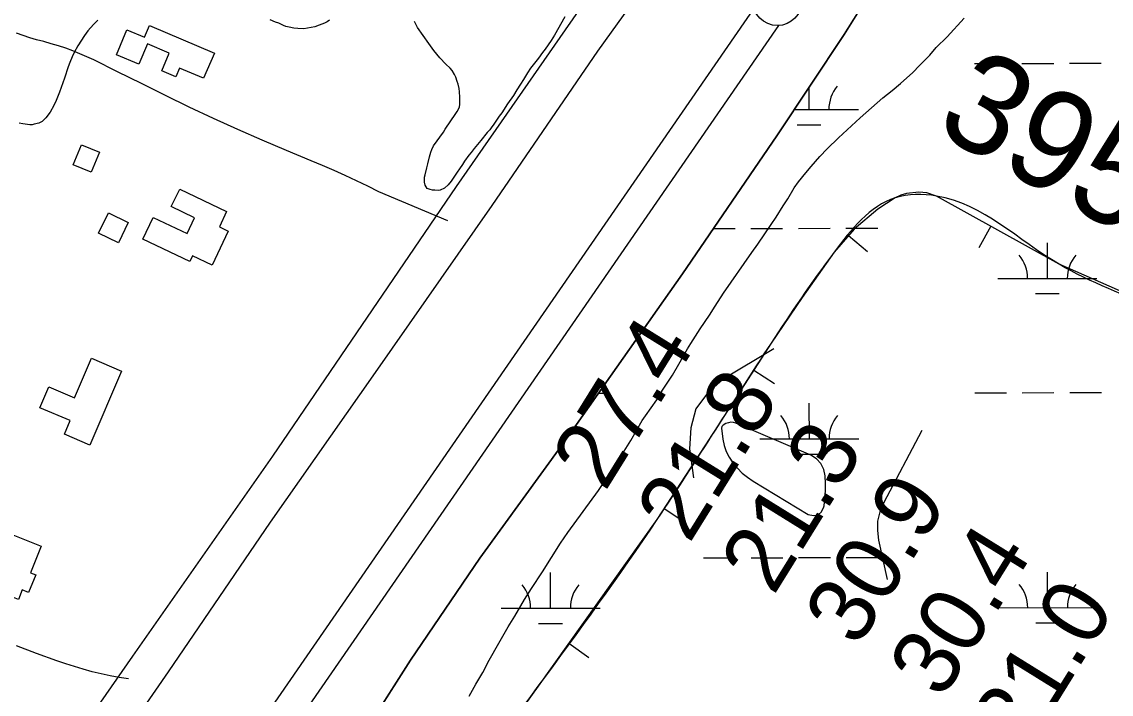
# Model space of a CAD drawing. Extents: x 3297716 to 3335574, y 688621 to 713991.
# Drawn here: x 3317812 to 3318912, y 694446 to 695125 of the extents above; entities that cross this region are included whole.
import ezdxf

# ---------------------------------------------------------------- set-up
doc = ezdxf.new("R2010")
doc.units = 0
for name, color, linetype in [('V-BLDG-OTLN', 7, 'Continuous'), ('V-BORW-LINE', 7, 'Continuous'), ('V-LEVE-TOET', 7, 'Continuous'), ('V-RIVR-RANG', 7, 'Continuous'), ('V-ROAD-CNTR', 7, 'Continuous'), ('V-SITE-VEGE', 7, 'Continuous'), ('V-SURV-IDEN', 7, 'Continuous'), ('V-SURV-LINE', 7, 'Continuous'), ('V-TOPO-MAJR', 7, 'Continuous'), ('V-TOPO-MINR', 7, 'Continuous'), ('V-WETL-SWMP', 7, 'Continuous')]:
    doc.layers.add(name, color=color, linetype=linetype)

msp = doc.modelspace()

# ---------------------------------------------------------------- linework, layer by layer
at = {"layer": 'V-BLDG-OTLN'}
for points in [[(3317941.1, 695121.1), (3318006.6, 695093.3), (3317995.8, 695067.8), (3317971.5, 695078.1), (3317967.8, 695069.4), (3317953.6, 695075.4), (3317961.1, 695093.2), (3317939.1, 695102.5), (3317930.4, 695081.9), (3317907.7, 695091.5), (3317918.4, 695116.8), (3317936.1, 695109.3)], [(3317872.3, 695000.6), (3317890.5, 694993.2), (3317882.2, 694972.8), (3317864, 694980.2)], [(3317981.9, 694882.7), (3317934.4, 694905.4), (3317944.8, 694927.2), (3317979, 694910.9), (3317986.7, 694926.8), (3317963.1, 694938.1), (3317971.6, 694955.8), (3318019, 694933.1), (3318011.7, 694917.8), (3318020.7, 694913.5), (3318004.3, 694879.1), (3317984.6, 694888.5)], [(3317889.7, 694911.4), (3317899.7, 694932), (3317919.7, 694922.2), (3317909.7, 694901.6)], [(3317912.9, 694771.9), (3317881, 694697.3), (3317855.2, 694708.3), (3317861, 694721.9), (3317830.4, 694735), (3317839.4, 694756.1), (3317865.3, 694745), (3317882.4, 694785)], [(3317808.8, 694541.1), (3317721.1, 694576.2), (3317732.1, 694603.8), (3317760.8, 694592.3), (3317769.4, 694613.6), (3317792.5, 694604.4), (3317794.7, 694610), (3317831.9, 694595.1), (3317821.1, 694568.2), (3317826.2, 694566.2), (3317819.1, 694548.4), (3317812.7, 694551)]]:
    msp.add_lwpolyline(points, close=True, dxfattribs=at)
at = {"layer": 'V-BORW-LINE'}
for p, q in [((3318790.5, 694918.3), (3318778.3, 694896.5)), ((3318646.9, 694909.1), (3318665.9, 694892.8)), ((3318551.1, 694773), (3318572.1, 694759.5)), ((3318460.6, 694633.1), (3318481.5, 694619.4)), ((3318364.5, 694497), (3318384.8, 694482.6))]:
    msp.add_line(p, q, dxfattribs=at)
msp.add_lwpolyline([(3318935.3, 694846.7), (3318859.4, 694879.9), (3318797.5, 694914.4), (3318735.8, 694948.8), (3318725.8, 694952.1), (3318717.7, 694952.9), (3318705.5, 694951.5), (3318699.6, 694949.6), (3318694.1, 694946.9), (3318676.3, 694935.4), (3318652.5, 694915.5), (3318632.3, 694892), (3318599.9, 694846.4), (3318568.6, 694800.2), (3318511.3, 694710.9), (3318453.4, 694622), (3318333.6, 694453.7), (3318213, 694285.8), (3318186, 694245.2), (3318159.9, 694204), (3318105.2, 694105.5), (3318055.5, 694015.9)], dxfattribs=at)
msp.add_spline([(3319332.2, 694473.6), (3319347, 694514.7), (3319330.1, 694574.1), (3319241.5, 694633.4), (3318959.4, 694833.3), (3318859.4, 694879.9), (3318735.8, 694948.8), (3318694.1, 694946.9), (3318632.3, 694892), (3318568.6, 694800.2), (3318453.4, 694622), (3318213, 694285.8), (3318159.9, 694204), (3318055.5, 694015.9)], degree=3, dxfattribs=at)
at = {"layer": 'V-LEVE-TOET'}
for points in [[(3317652, 694015.5), (3317668.6, 694039.1), (3317749.2, 694161.4), (3317845.8, 694302.5), (3317960.2, 694468), (3318063.4, 694619.5), (3318169.3, 694770.4), (3318287.1, 694939.4), (3318393.6, 695095.1), (3318461.1, 695189.1), (3318541.9, 695305.9), (3318564.2, 695344), (3318624, 695448.7), (3318714.8, 695601.3), (3318772.1, 695698.4), (3318845.7, 695826.7), (3318919.3, 695952.9), (3318961.3, 696029.8)], [(3319158, 696012), (3319131.1, 695962.5), (3319107, 695922.2), (3319070.4, 695855.9), (3319013.2, 695748.1), (3318951.2, 695629.8), (3318896.2, 695534.7), (3318856.5, 695470.4), (3318811.7, 695392.9), (3318760.5, 695301.1), (3318693.1, 695193.2), (3318642.5, 695111.9), (3318574.5, 695009.8), (3318479.1, 694870.1), (3318359.3, 694699.7), (3318274.7, 694583.1), (3318204.5, 694479.8), (3318137.2, 694374.3), (3318078.9, 694292.9), (3318012.6, 694201), (3317924.3, 694059.4), (3317893.4, 694015.8)]]:
    msp.add_lwpolyline(points, dxfattribs=at)
at = {"layer": 'V-ROAD-CNTR'}
for points in [[(3318232.4, 696770.3), (3318649.1, 696595.7), (3318972.2, 696436.3), (3319007.9, 696418.5), (3319026.2, 696396.9), (3319039.9, 696371.9), (3319042.2, 696353.2), (3319028.3, 696304.5), (3318891, 696007.4), (3318771, 695795.6), (3318724, 695707.8), (3318668.7, 695606.4), (3318611.5, 695513.5), (3318524, 695352.8), (3318400.7, 695174.7), (3318250.6, 694958.6), (3318065.2, 694686.1), (3317923.9, 694483.9), (3317766.8, 694258.3), (3317645.7, 694083.5), (3317602.2, 694018.4)], [(3318242.2, 694923.8), (3318219, 694933.6), (3318195.8, 694943.4), (3318172.7, 694953.1), (3318161.5, 694958.8), (3318150.2, 694964.3), (3318138.8, 694969.6), (3318127.4, 694974.7), (3318115.9, 694979.6), (3318104.2, 694984.4), (3318079.5, 694994.7), (3318054.8, 695005.3), (3318030.2, 695016.2), (3318005.7, 695027.3), (3317981.3, 695038.6), (3317957.2, 695050.5), (3317933, 695062.5), (3317908.9, 695074.4), (3317884.8, 695086.4), (3317877.8, 695089.6), (3317870.8, 695092.6), (3317863.7, 695095.5), (3317856.5, 695098.1), (3317849.3, 695100.5), (3317842, 695102.7), (3317834.6, 695104.8), (3317827.2, 695106.6), (3317820.3, 695108.7), (3317813.6, 695111), (3317806.9, 695113.5)], [(3317919.8, 694461), (3317910.6, 694462.5), (3317901.5, 694464.2), (3317892.4, 694466.2), (3317883.3, 694468.3), (3317874.3, 694470.7), (3317865.4, 694473.4), (3317856.5, 694476.2), (3317847.7, 694479.3), (3317827.2, 694486.7), (3317806.8, 694494.3)]]:
    msp.add_lwpolyline(points, dxfattribs=at)
at = {"layer": 'V-SITE-VEGE'}
for p, q in [((3318746.3, 695109.8), (3318763.6, 695128.6)), ((3318735.5, 695098.9), (3318746.3, 695109.8)), ((3318718.6, 695080.8), (3318729.1, 695091.3)), ((3318729.1, 695091.3), (3318735.5, 695098.9)), ((3318711.8, 695073.6), (3318718.6, 695080.8)), ((3318699.5, 695062.6), (3318711.8, 695073.6)), ((3318690.9, 695055.4), (3318699.5, 695062.6)), ((3318658.7, 695027.8), (3318681.5, 695047.9)), ((3318681.5, 695047.9), (3318690.9, 695055.4)), ((3318636.7, 695007.7), (3318658.7, 695027.8)), ((3318625.2, 694996.4), (3318636.7, 695007.7)), ((3318618, 694988.9), (3318625.2, 694996.4)), ((3318609, 694978.7), (3318618, 694988.9)), ((3318596.5, 694963.3), (3318603.7, 694972.3)), ((3318603.7, 694972.3), (3318609, 694978.7)), ((3318591.9, 694957), (3318596.5, 694963.3)), ((3318585.5, 694946.1), (3318591.9, 694957)), ((3318573.8, 694927.4), (3318580.9, 694939)), ((3318580.9, 694939), (3318585.5, 694946.1)), ((3318568.8, 694919.9), (3318573.8, 694927.4)), ((3318555.2, 694900.1), (3318568.8, 694919.9)), ((3318520.7, 694850.6), (3318549.2, 694891.8)), ((3318549.2, 694891.8), (3318555.2, 694900.1)), ((3318512.1, 694837.5), (3318520.7, 694850.6)), ((3318506.4, 694828.6), (3318512.1, 694837.5)), ((3318497.2, 694814.7), (3318506.4, 694828.6)), ((3318487.6, 694799.8), (3318497.2, 694814.7)), ((3318475.5, 694778.8), (3318484.4, 694794.5)), ((3318484.4, 694794.5), (3318487.6, 694799.8)), ((3318469.2, 694768), (3318475.5, 694778.8)), ((3318459.2, 694752.7), (3318469.2, 694768)), ((3318453.2, 694742.9), (3318459.2, 694752.7)), ((3318441.8, 694726.8), (3318453.2, 694742.9)), ((3318438.6, 694722), (3318441.8, 694726.8)), ((3318427.2, 694701.8), (3318438.6, 694722)), ((3318420.5, 694691), (3318427.2, 694701.8)), ((3318409.5, 694674.1), (3318420.5, 694691)), ((3318402, 694662.5), (3318409.5, 694674.1)), ((3318394.5, 694651.3), (3318402, 694662.5)), ((3318363.5, 694608.9), (3318394.5, 694651.3)), ((3318356, 694598.1), (3318363.5, 694608.9)), ((3318337.9, 694569.3), (3318356, 694598.1)), ((3318326.8, 694552.4), (3318337.9, 694569.3)), ((3318319.7, 694541.2), (3318326.8, 694552.4)), ((3318309.8, 694524.4), (3318319.7, 694541.2)), ((3318303.1, 694513.6), (3318309.8, 694524.4)), ((3318293.9, 694497.1), (3318303.1, 694513.6)), ((3318284, 694479.9), (3318293.9, 694497.1)), ((3318277.6, 694467.6), (3318284, 694479.9)), ((3318270.5, 694455.7), (3318277.6, 694467.6)), ((3318263.8, 694443.7), (3318270.5, 694455.7))]:
    msp.add_line(p, q, dxfattribs=at)
for points in [[(3317889, 695126.6), (3317884.5, 695122), (3317878.9, 695115.8), (3317875.4, 695111.1), (3317868.7, 695100.7), (3317865.2, 695093.9), (3317863.2, 695089.6), (3317860.6, 695083.8), (3317858.9, 695079.5), (3317855.2, 695067.9), (3317850.4, 695053.9), (3317846.9, 695045.3), (3317844.6, 695040.4), (3317840.8, 695033.6), (3317836.4, 695027.8), (3317832.6, 695024), (3317829.3, 695022.4), (3317824.7, 695021.4), (3317822.6, 695020.8), (3317820.2, 695020.7), (3317817.8, 695021), (3317813.2, 695021.8), (3317809.6, 695022.6)], [(3318122.7, 695126.6), (3318120.6, 695124.8), (3318117.9, 695123.5), (3318112.5, 695121.3), (3318108, 695119.9), (3318096.8, 695117.9), (3318090.8, 695118), (3318086.8, 695118.5), (3318082, 695119.3), (3318078.9, 695120.2), (3318076.5, 695121), (3318071.6, 695123.3), (3318068.2, 695124.5), (3318063, 695126.8)], [(3318360.5, 695129.7), (3318350, 695111.3), (3318346.5, 695105.9), (3318340.6, 695097.3), (3318337.8, 695093.8), (3318333.7, 695088.2), (3318325.9, 695077.9), (3318322.8, 695073.3), (3318318.6, 695066.4), (3318315.7, 695062), (3318312, 695056), (3318308.5, 695050.5), (3318302.7, 695042), (3318296.8, 695033), (3318294.2, 695029.5), (3318289.5, 695022.6), (3318288.1, 695020.4), (3318286.9, 695018.6), (3318284.6, 695015.7), (3318282.1, 695013), (3318275.5, 695004.8), (3318268.9, 694996.9), (3318265.9, 694992.8), (3318263.6, 694990.1), (3318259.1, 694984), (3318257, 694980.8), (3318254.1, 694976.2), (3318251.6, 694972.8), (3318245.7, 694964), (3318242.5, 694960.1), (3318238.9, 694956.9), (3318234.7, 694954.7), (3318232.7, 694954.5), (3318229.3, 694954.6), (3318227, 694954.8), (3318224.6, 694955.4), (3318221.6, 694956.6), (3318219.3, 694959.9), (3318218.7, 694962.7), (3318218.9, 694967.8), (3318219.3, 694970.3), (3318221.2, 694977.3), (3318222.2, 694981.4), (3318223.7, 694988.4), (3318225, 694993.2), (3318226.2, 694995.9), (3318228, 694999.4), (3318237.9, 695013.3), (3318239.7, 695016.5), (3318250.3, 695032.1), (3318251.8, 695034.2), (3318253.1, 695036.7), (3318254, 695039), (3318254.3, 695041.3), (3318254.4, 695048.8), (3318254.2, 695054), (3318253.6, 695057.3), (3318252.7, 695061.7), (3318251.9, 695064.7), (3318250.3, 695068.9), (3318249.2, 695071.5), (3318246.7, 695075.7), (3318244.6, 695078.1), (3318240.4, 695082.1), (3318234.3, 695088.4), (3318228.2, 695095.7), (3318223, 695103), (3318211.8, 695119.1), (3318210.3, 695121.8), (3318208.6, 695125)]]:
    msp.add_lwpolyline(points, dxfattribs=at)
at = {"layer": 'V-SURV-LINE'}
for points in [[(3317776.6, 694015.6), (3318551.4, 695138.1)], [(3318576.1, 695121.1), (3317813.1, 694015.7)]]:
    msp.add_lwpolyline(points, dxfattribs=at)
msp.add_circle((3318575.1, 695146.1), 25, dxfattribs=at)
at = {"layer": 'V-TOPO-MAJR'}
for points in [[(3318571.5, 694794.4), (3318520.4, 694763.9), (3318504.5, 694749.8), (3318492.8, 694733.7), (3318487.5, 694714.6), (3318486.3, 694693.4), (3318490.2, 694664.1)], [(3318686.2, 694561.3), (3318677.4, 694601.1), (3318676.3, 694610.8), (3318676.6, 694620.4), (3318678.8, 694629.7), (3318682.5, 694638.8), (3318721.1, 694712.4)]]:
    msp.add_lwpolyline(points, dxfattribs=at)
at = {"layer": 'V-TOPO-MINR'}
msp.add_lwpolyline([(3318523.3, 694690.6), (3318526.3, 694684.9), (3318529.9, 694679.4), (3318530.2, 694679), (3318534.7, 694673.8), (3318539.6, 694669), (3318544.9, 694664.7), (3318550.6, 694660.8), (3318606.1, 694627.1), (3318611.5, 694626), (3318616.2, 694626.6), (3318619.5, 694629.9), (3318622.1, 694634.8), (3318622.3, 694636), (3318623.1, 694643.5), (3318623.6, 694651), (3318623.6, 694658.5), (3318623.4, 694666), (3318621.8, 694672.7), (3318619, 694678.6), (3318614.5, 694683.2), (3318608.7, 694686.9), (3318533.2, 694719.3), (3318530.6, 694720), (3318528.1, 694720.3), (3318525.6, 694719.8), (3318523.1, 694719), (3318520.2, 694717.4), (3318518.8, 694716.1), (3318518.5, 694714.2), (3318519.9, 694703.2), (3318521.3, 694696.8), (3318523.3, 694690.6)], dxfattribs=at)
at = {"layer": 'V-WETL-SWMP'}
for p, q in [((3318642.5, 695111.9), (3318693.1, 695193.2)), ((3318574.4, 695009.8), (3318642.5, 695111.9)), ((3318774, 695082.8), (3318806, 695082.8)), ((3318822, 695082.8), (3318854, 695082.8)), ((3318870, 695082.9), (3318902, 695082.9)), ((3318607, 695036.2), (3318607, 695058.6)), ((3318592.1, 695036.2), (3318657, 695036.3)), ((3318595, 695020.8), (3318619, 695020.8)), ((3318479.1, 694870.1), (3318574.4, 695009.8)), ((3318510.5, 694916.1), (3318532.3, 694916.1)), ((3318548.3, 694916.1), (3318580.3, 694916.1)), ((3318596.3, 694916.1), (3318628.3, 694916.2)), ((3318644.3, 694916.2), (3318676.3, 694916.2)), ((3318847.6, 694865.6), (3318847.6, 694901.6)), ((3318359.3, 694699.7), (3318479.1, 694870.1)), ((3318797.6, 694865.6), (3318897.6, 694865.6)), ((3318835.6, 694850.2), (3318859.6, 694850.2)), ((3318394.5, 694749.8), (3318400.4, 694749.8)), ((3318774.3, 694750.1), (3318806.3, 694750.1)), ((3318822.3, 694750.1), (3318854.3, 694750.2)), ((3318870.3, 694750.2), (3318902.3, 694750.2)), ((3318607.3, 694703.5), (3318607.2, 694739.5)), ((3318274.7, 694583.1), (3318359.3, 694699.7)), ((3318557.3, 694703.5), (3318657.3, 694703.6)), ((3318595.3, 694688.1), (3318619.3, 694688.1)), ((3318596.5, 694583.5), (3318628.5, 694583.5)), ((3318644.5, 694583.5), (3318676.5, 694583.5)), ((3318204.5, 694479.8), (3318274.7, 694583.1)), ((3318500.5, 694583.4), (3318532.5, 694583.4)), ((3318548.5, 694583.4), (3318580.5, 694583.4)), ((3318346, 694532.5), (3318346, 694568.5)), ((3318847.9, 694532.9), (3318847.9, 694568.9)), ((3318296, 694532.5), (3318396, 694532.5)), ((3318797.9, 694532.9), (3318897.9, 694533)), ((3318835.9, 694517.5), (3318859.9, 694517.5)), ((3318334, 694517.1), (3318358, 694517.1)), ((3318137.2, 694374.3), (3318204.5, 694479.8))]:
    msp.add_line(p, q, dxfattribs=at)
for centre, start, end in [((3318662.2, 695036.7), 139.2762, 180.8199), ((3318792.4, 694866), 359.2762, 40.8199), ((3318902.9, 694866.1), 139.2762, 180.8199), ((3318552, 694704), 359.2762, 40.8199), ((3318662.5, 694704.1), 139.2762, 180.8199), ((3318290.7, 694532.9), 359.2762, 40.8199), ((3318401.2, 694533), 139.2762, 180.8199), ((3318792.6, 694533.4), 359.2762, 40.8199), ((3318903.1, 694533.4), 139.2762, 180.8199)]:
    msp.add_arc(centre, 35.2, start, end, dxfattribs=at)

# ---------------------------------------------------------------- texts
at = {"layer": 'V-RIVR-RANG'}
for s, p in [('27.4', (3318400.9, 694649.2)), ('21.8', (3318486, 694596.7)), ('21.3', (3318571.1, 694544.2)), ('30.9', (3318656, 694491.5)), ('30.4', (3318741.3, 694439.2)), ('31.0', (3318824.9, 694384.2)), ('31.0', (3318910, 694331.7))]:
    msp.add_text(s, height=67, rotation=58.1883, dxfattribs=at).set_placement(p)
at = {"layer": 'V-SURV-IDEN'}
msp.add_text('3951+68.5', height=100, rotation=331.232, dxfattribs=at).set_placement((3318731.5, 695014.8))

doc.saveas('drawing.dxf')
